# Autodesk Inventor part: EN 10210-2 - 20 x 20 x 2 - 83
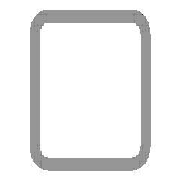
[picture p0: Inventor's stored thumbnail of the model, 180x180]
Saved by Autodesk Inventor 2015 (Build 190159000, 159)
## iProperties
Created: 2015-05
Part Number: EN 10210-2 - 20 x 20 x 2 - 83
Material: Steel, Mild
Description: Tube
Document SubType Name: Modeling
Standard: DIN
Designer: TREINA6
Standard Revision: 1997
Standards Organization: DIN
Language: en-US
Size Designation: 20 x 20 x 2
Categories: <MemberInstance><Categories><Category DisplayName="Structural Shapes" InternalName="089c4875-fa83-4c05-b084-43b9cc11f5ed" Mnemonic="GRDR"><CategoryParameter Dis
Stock Number: 20 x 20 x 2
Density: 7.85 g/cm^3
Appearance: Semi-Polished
IsCustomPart: 1
_CCFamilyMember: 1
_CCFamilyDisplayName: DIN EN 10210-2 (Square) - Tube
_FrameMemberDoc: Frame Member File
_Version: 15.0.0
_GetPNFromCC: 1
Author: TREINA6
G_L: 83,000 mm
G_W: 20,000 mm
G_H: 20,000 mm
+EC8849D6-931A-4923-8C4A-CF8D3011DE93+CUTDETAIL1: Cut
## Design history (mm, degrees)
node "Start plane"
node "End plane"
sketch "Sketch"
  geometry: L1 (-10, -7)-(-10, 7); L2 (-7, 10)-(7, 10); L3 (10, 7)-(10, -7); L4 (7, -10)-(-7, -10); L5 (-7, 8)-(7, 8); L6 (8, 7)-(8, -7); L7 (7, -8)-(-7, -8); L8 (-8, -7)-(-8, 7); L9 (0, 14.87)-(0, -14.87) reference; L10 (-14.87, 0)-(14.87, 0) reference; A1 r 3 centre (-7, -7) between (-10, -7) and (-7, -10); A2 r 3 centre (-7, 7) between (-7, 10) and (-10, 7); A3 r 3 centre (7, 7) between (10, 7) and (7, 10); A4 r 3 centre (7, -7) between (7, -10) and (10, -7); A5 r 1 centre (-7, 7) between (-7, 8) and (-8, 7); A6 r 1 centre (7, 7) between (8, 7) and (7, 8); A7 r 1 centre (7, -7) between (7, -8) and (8, -7); A8 r 1 centre (-7, -7) between (-8, -7) and (-7, -8)
  constraints: 16 end point, 16 point on circle, 8 centre point, 8 tangent, 4 parallel, 3 equal radius, 2 perpendicular, 7 other
  dimensions: "d7" = 3 radius of A1 (= G_IR); "d10" = 20 distance between parallel lines of L2 L4 (= G_H); "d11" = 20 distance between parallel lines of L1 L3 (= G_W); "d12" = 2 distance between parallel lines of L3 L6 (= G_T); "d15" = 10 distance between parallel lines of L2 L10 (= 0.5 x d10); "d16" = 10 distance between parallel lines of L9 L3 (= 0.5 x d11)
extrude "Body" new body sketch "Sketch" stored distance "d3" = 83 (= G_L); taper "d4" = 0 deg
node "Driven Length"
  sketch "Sketch3"
    geometry: L1 (0, 0)-(10, 0) reference
    constraints: 2 end point, 1 horizontal
  workplane "Work Plane3"
  sketch "Sketch4"
    geometry: L1 (-2, 20)-(12, 20) reference; L2 (-2, 103)-(12, 103) reference
    dimensions: "d18" = 83 distance between parallel lines of L1 L2 (derived)
workplane "Work Plane4"
split "Split1"
body "Solid1"
other parameters: "G_W" = 20 [user parameter; used in 1 equation term], "G_H" = 20 [user parameter; used in 1 equation term], "G_T" = 2 [user parameter; used in 1 equation term], "G_IR" = 3 [user parameter; used in 1 equation term], "G_L" = 83 (= d18) [user parameter; used in 1 equation term], "G_OFFSET_END" = 0 [user parameter; used in 1 equation term], "d14" = 103 (= G_OFFSET_END + B_L), "B_L" = 103 [user parameter; used in 1 equation term], "d17" = 90 deg
